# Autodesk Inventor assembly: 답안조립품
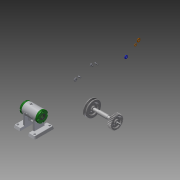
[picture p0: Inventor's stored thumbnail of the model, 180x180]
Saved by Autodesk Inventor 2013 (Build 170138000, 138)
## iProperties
Created: 2016-07
Part Number: 답안조립품
Document SubType Name: Assembly
Designer: WINDOWS7
Author: WINDOWS7
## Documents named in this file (16)
- C:\Users\WINDOWS7\Desktop\460708V1001\답안조립품.iam
- C:\Users\WINDOWS7\Desktop\460708V1001\1-본체.ipt
- C:\Users\WINDOWS7\Desktop\460708V1001\V벨트풀리.ipt
- C:\Users\WINDOWS7\Desktop\460708V1001\너트 M 8.ipt
- C:\Users\WINDOWS7\Desktop\460708V1001\니플 M 6 x 0.75.ipt
- C:\Users\WINDOWS7\Desktop\460708V1001\베어링 15 x 32 x 9.ipt
- C:\Users\WINDOWS7\Desktop\460708V1001\볼트 M 6 x 8.ipt
- C:\Users\WINDOWS7\Desktop\460708V1001\볼트 M4 x 12.ipt
- C:\Users\WINDOWS7\Desktop\460708V1001\스퍼기어.ipt
- C:\Users\WINDOWS7\Desktop\460708V1001\스프링와셔 8.ipt
- C:\Users\WINDOWS7\Desktop\460708V1001\오일 실 15 25 7.ipt
- C:\Users\WINDOWS7\Desktop\460708V1001\와셔 6x11.5.ipt
- C:\Users\WINDOWS7\Desktop\460708V1001\와셔 8x17.ipt
- C:\Users\WINDOWS7\Desktop\460708V1001\축.ipt
- C:\Users\WINDOWS7\Desktop\460708V1001\커버.ipt
- C:\Users\WINDOWS7\Desktop\460708V1001\키 3 x 3 x 12.ipt
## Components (5 placed, 4 different names)
1. 1-본체:1
2. V벨트풀리:1
3. KS B 2023 6002 - 15 x 32 x 9:1
4. ISO 4762 M4 x 12:1
5. KS B 2023 6002 - 15 x 32 x 9:2
